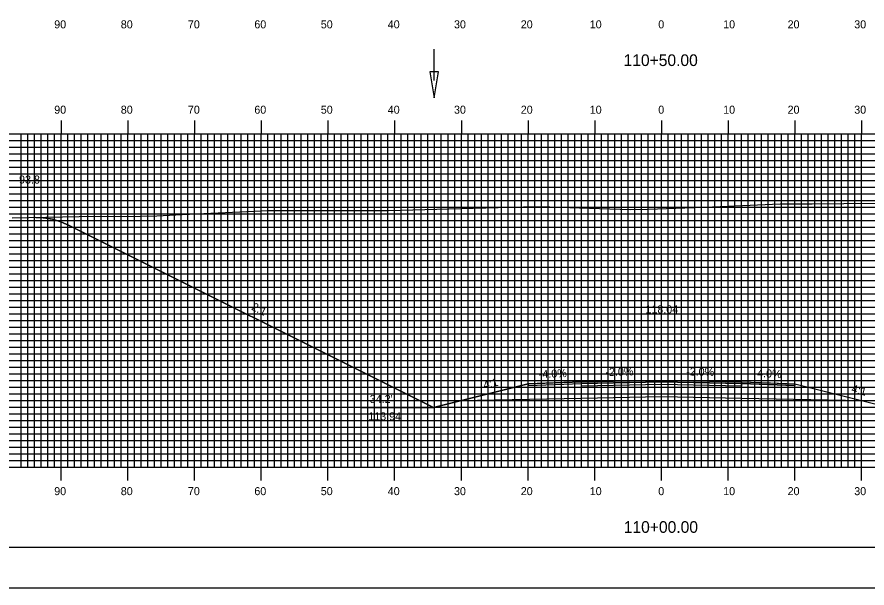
# Model space of a CAD drawing. Extents: x 1769268 to 1769611, y 442591 to 442811.
# Drawn here: x 1769336.9 to 1769464.3, y 442590.5 to 442676.2 of the extents above; entities that cross this region are included whole.
import ezdxf

# ---------------------------------------------------------------- set-up
doc = ezdxf.new("R2010")
doc.units = 0
for name, color, linetype in [('ANNOTATION', 7, 'Continuous'), ('BORDER', 7, 'Continuous'), ('D_Drainage_Ditch_Line', 7, 'Continuous'), ('D_Roadway_Centerline', 7, 'Continuous'), ('D_Roadway_Centerline_Text', 7, 'Continuous'), ('D_Roadway_Edge_Shoulder', 7, 'Continuous'), ('D_Roadway_Edge_TW', 7, 'Continuous'), ('D_Roadway_Pavement', 7, 'Continuous'), ('D_Roadway_SlopeLines', 7, 'Continuous'), ('D_Roadway_SubGrade', 7, 'Continuous'), ('D_Text_Standard', 7, 'Continuous'), ('H_V ANNOTATION', 7, 'Continuous'), ('MAJOR', 7, 'Continuous'), ('MINOR', 7, 'Continuous'), ('PDRAIN', 7, 'Continuous'), ('PLOT BOUNDARY', 7, 'Continuous'), ('S_Roadway_Centerline', 7, 'Continuous')]:
    doc.layers.add(name, color=color, linetype=linetype)

msp = doc.modelspace()

# ---------------------------------------------------------------- linework, layer by layer
at = {"layer": 'BORDER'}
msp.add_lwpolyline([(1769283.9, 442596.67), (1769603.9, 442596.67), (1769603.9, 442806.67), (1769283.9, 442806.67)], close=True, dxfattribs=at)
at = {"layer": 'D_Drainage_Ditch_Line'}
msp.add_line((1769399.44, 442666.66), (1769399.44, 442671.36), dxfattribs=at)
msp.add_lwpolyline([(1769400.1, 442667.97), (1769398.78, 442667.97), (1769399.44, 442664.03)], close=True, dxfattribs=at)
at = {"layer": 'D_Roadway_Centerline'}
msp.add_lwpolyline([(1769339.7, 442646.12), (1769340.82, 442646.07), (1769340.95, 442646.06), (1769341.19, 442646.02), (1769342.2, 442645.84), (1769342.71, 442645.69), (1769343.45, 442645.46), (1769344.7, 442644.92), (1769399.32, 442617.6), (1769399.33, 442617.6), (1769403.33, 442618.6), (1769405.69, 442619.19), (1769413.5, 442621.15), (1769417.29, 442621.3), (1769421.5, 442621.47), (1769433.5, 442621.71), (1769433.5, 442621.71), (1769445.5, 442621.47), (1769449.86, 442621.29), (1769453.5, 442621.15), (1769457.11, 442620.24), (1769463.68, 442618.6), (1769467.68, 442617.6)], dxfattribs=at)
at = {"layer": 'D_Roadway_Edge_Shoulder'}
for points in [[(1769421.5, 442621.47), (1769413.5, 442621.15), (1769413.5, 442620.9), (1769421.5, 442621.22)], [(1769445.5, 442621.47), (1769453.5, 442621.15), (1769453.5, 442620.9), (1769445.5, 442621.22)]]:
    msp.add_lwpolyline(points, close=True, dxfattribs=at)
at = {"layer": 'D_Roadway_Edge_TW'}
msp.add_lwpolyline([(1769421.5, 442621.22), (1769421.5, 442621.47), (1769433.5, 442621.71), (1769445.5, 442621.47), (1769445.5, 442621.22), (1769433.5, 442621.46)], close=True, dxfattribs=at)
at = {"layer": 'D_Roadway_Pavement'}
msp.add_lwpolyline([(1769421.5, 442620.8), (1769421.5, 442621.22), (1769433.5, 442621.46), (1769445.5, 442621.22), (1769445.5, 442620.8), (1769433.5, 442621.04)], close=True, dxfattribs=at)
at = {"layer": 'D_Roadway_SlopeLines'}
for points in [[(1769399.33, 442617.6), (1769344.7, 442644.92), (1769343.45, 442645.46), (1769342.2, 442645.84), (1769340.95, 442646.06), (1769339.7, 442646.12)], [(1769413.5, 442621.15), (1769399.33, 442617.6)], [(1769453.5, 442621.15), (1769467.68, 442617.6)]]:
    msp.add_lwpolyline(points, dxfattribs=at)
at = {"layer": 'D_Roadway_SubGrade'}
msp.add_lwpolyline([(1769421.5, 442618.97), (1769403.33, 442618.6), (1769413.5, 442621.15), (1769413.5, 442620.9), (1769421.5, 442621.22), (1769433.5, 442621.46), (1769445.5, 442621.22), (1769453.5, 442620.9), (1769453.5, 442621.15), (1769463.68, 442618.6), (1769445.5, 442618.97), (1769433.5, 442619.21)], close=True, dxfattribs=at)
at = {"layer": 'MAJOR'}
for p, q in [((1769343.5, 442660.67), (1769343.5, 442658.67)), ((1769353.5, 442660.67), (1769353.5, 442658.67)), ((1769363.5, 442660.67), (1769363.5, 442658.67)), ((1769373.5, 442660.67), (1769373.5, 442658.67)), ((1769383.5, 442660.67), (1769383.5, 442658.67)), ((1769393.5, 442660.67), (1769393.5, 442658.67)), ((1769403.5, 442660.67), (1769403.5, 442658.67)), ((1769413.5, 442660.67), (1769413.5, 442658.67)), ((1769423.5, 442660.67), (1769423.5, 442658.67)), ((1769433.5, 442660.67), (1769433.5, 442658.67)), ((1769443.5, 442660.67), (1769443.5, 442658.67)), ((1769453.5, 442660.67), (1769453.5, 442658.67)), ((1769463.5, 442660.67), (1769463.5, 442658.67)), ((1769293.5, 442658.67), (1769573.5, 442658.67)), ((1769293.5, 442658.67), (1769573.5, 442658.67)), ((1769343.5, 442608.67), (1769343.5, 442658.67)), ((1769353.5, 442608.67), (1769353.5, 442658.67)), ((1769363.5, 442608.67), (1769363.5, 442658.67)), ((1769373.5, 442608.67), (1769373.5, 442658.67)), ((1769383.5, 442608.67), (1769383.5, 442658.67)), ((1769393.5, 442608.67), (1769393.5, 442658.67)), ((1769403.5, 442608.67), (1769403.5, 442658.67)), ((1769413.5, 442608.67), (1769413.5, 442658.67)), ((1769423.5, 442608.67), (1769423.5, 442658.67)), ((1769433.5, 442608.67), (1769433.5, 442658.67)), ((1769443.5, 442608.67), (1769443.5, 442658.67)), ((1769453.5, 442608.67), (1769453.5, 442658.67)), ((1769463.5, 442608.67), (1769463.5, 442658.67)), ((1769293.5, 442653.67), (1769573.5, 442653.67)), ((1769293.5, 442648.67), (1769573.5, 442648.67)), ((1769293.5, 442643.67), (1769573.5, 442643.67)), ((1769293.5, 442638.67), (1769573.5, 442638.67)), ((1769293.5, 442633.67), (1769573.5, 442633.67)), ((1769293.5, 442628.67), (1769573.5, 442628.67)), ((1769293.5, 442623.67), (1769573.5, 442623.67)), ((1769293.5, 442618.67), (1769573.5, 442618.67)), ((1769293.5, 442613.67), (1769573.5, 442613.67)), ((1769293.5, 442608.67), (1769573.5, 442608.67)), ((1769293.5, 442608.67), (1769573.5, 442608.67)), ((1769343.5, 442606.66), (1769343.5, 442608.67)), ((1769353.5, 442606.66), (1769353.5, 442608.67)), ((1769363.5, 442606.66), (1769363.5, 442608.67)), ((1769373.5, 442606.66), (1769373.5, 442608.67)), ((1769383.5, 442606.66), (1769383.5, 442608.67)), ((1769393.5, 442606.66), (1769393.5, 442608.67)), ((1769403.5, 442606.66), (1769403.5, 442608.67)), ((1769413.5, 442606.66), (1769413.5, 442608.67)), ((1769423.5, 442606.66), (1769423.5, 442608.67)), ((1769433.5, 442606.66), (1769433.5, 442608.67)), ((1769443.5, 442606.66), (1769443.5, 442608.67)), ((1769453.5, 442606.66), (1769453.5, 442608.67)), ((1769463.5, 442606.66), (1769463.5, 442608.67))]:
    msp.add_line(p, q, dxfattribs=at)
at = {"layer": 'MINOR'}
for p, q in [((1769337.5, 442608.67), (1769337.5, 442658.67)), ((1769338.5, 442608.67), (1769338.5, 442658.67)), ((1769339.5, 442608.67), (1769339.5, 442658.67)), ((1769340.5, 442608.67), (1769340.5, 442658.67)), ((1769341.5, 442608.67), (1769341.5, 442658.67)), ((1769342.5, 442608.67), (1769342.5, 442658.67)), ((1769344.5, 442608.67), (1769344.5, 442658.67)), ((1769345.5, 442608.67), (1769345.5, 442658.67)), ((1769346.5, 442608.67), (1769346.5, 442658.67)), ((1769347.5, 442608.67), (1769347.5, 442658.67)), ((1769348.5, 442608.67), (1769348.5, 442658.67)), ((1769349.5, 442608.67), (1769349.5, 442658.67)), ((1769350.5, 442608.67), (1769350.5, 442658.67)), ((1769351.5, 442608.67), (1769351.5, 442658.67)), ((1769352.5, 442608.67), (1769352.5, 442658.67)), ((1769354.5, 442608.67), (1769354.5, 442658.67)), ((1769355.5, 442608.67), (1769355.5, 442658.67)), ((1769356.5, 442608.67), (1769356.5, 442658.67)), ((1769357.5, 442608.67), (1769357.5, 442658.67)), ((1769358.5, 442608.67), (1769358.5, 442658.67)), ((1769359.5, 442608.67), (1769359.5, 442658.67)), ((1769360.5, 442608.67), (1769360.5, 442658.67)), ((1769361.5, 442608.67), (1769361.5, 442658.67)), ((1769362.5, 442608.67), (1769362.5, 442658.67)), ((1769364.5, 442608.67), (1769364.5, 442658.67)), ((1769365.5, 442608.67), (1769365.5, 442658.67)), ((1769366.5, 442608.67), (1769366.5, 442658.67)), ((1769367.5, 442608.67), (1769367.5, 442658.67)), ((1769368.5, 442608.67), (1769368.5, 442658.67)), ((1769369.5, 442608.67), (1769369.5, 442658.67)), ((1769370.5, 442608.67), (1769370.5, 442658.67)), ((1769371.5, 442608.67), (1769371.5, 442658.67)), ((1769372.5, 442608.67), (1769372.5, 442658.67)), ((1769374.5, 442608.67), (1769374.5, 442658.67)), ((1769375.5, 442608.67), (1769375.5, 442658.67)), ((1769376.5, 442608.67), (1769376.5, 442658.67)), ((1769377.5, 442608.67), (1769377.5, 442658.67)), ((1769378.5, 442608.67), (1769378.5, 442658.67)), ((1769379.5, 442608.67), (1769379.5, 442658.67)), ((1769380.5, 442608.67), (1769380.5, 442658.67)), ((1769381.5, 442608.67), (1769381.5, 442658.67)), ((1769382.5, 442608.67), (1769382.5, 442658.67)), ((1769384.5, 442608.67), (1769384.5, 442658.67)), ((1769385.5, 442608.67), (1769385.5, 442658.67)), ((1769386.5, 442608.67), (1769386.5, 442658.67)), ((1769387.5, 442608.67), (1769387.5, 442658.67)), ((1769388.5, 442608.67), (1769388.5, 442658.67)), ((1769389.5, 442608.67), (1769389.5, 442658.67)), ((1769390.5, 442608.67), (1769390.5, 442658.67)), ((1769391.5, 442608.67), (1769391.5, 442658.67)), ((1769392.5, 442608.67), (1769392.5, 442658.67)), ((1769394.5, 442608.67), (1769394.5, 442658.67)), ((1769395.5, 442608.67), (1769395.5, 442658.67)), ((1769396.5, 442608.67), (1769396.5, 442658.67)), ((1769397.5, 442608.67), (1769397.5, 442658.67)), ((1769398.5, 442608.67), (1769398.5, 442658.67)), ((1769399.5, 442608.67), (1769399.5, 442658.67)), ((1769400.5, 442608.67), (1769400.5, 442658.67)), ((1769401.5, 442608.67), (1769401.5, 442658.67)), ((1769402.5, 442608.67), (1769402.5, 442658.67)), ((1769404.5, 442608.67), (1769404.5, 442658.67)), ((1769405.5, 442608.67), (1769405.5, 442658.67)), ((1769406.5, 442608.67), (1769406.5, 442658.67)), ((1769407.5, 442608.67), (1769407.5, 442658.67)), ((1769408.5, 442608.67), (1769408.5, 442658.67)), ((1769409.5, 442608.67), (1769409.5, 442658.67)), ((1769410.5, 442608.67), (1769410.5, 442658.67)), ((1769411.5, 442608.67), (1769411.5, 442658.67)), ((1769412.5, 442608.67), (1769412.5, 442658.67)), ((1769414.5, 442608.67), (1769414.5, 442658.67)), ((1769415.5, 442608.67), (1769415.5, 442658.67)), ((1769416.5, 442608.67), (1769416.5, 442658.67)), ((1769417.5, 442608.67), (1769417.5, 442658.67)), ((1769418.5, 442608.67), (1769418.5, 442658.67)), ((1769419.5, 442608.67), (1769419.5, 442658.67)), ((1769420.5, 442608.67), (1769420.5, 442658.67)), ((1769421.5, 442608.67), (1769421.5, 442658.67)), ((1769422.5, 442608.67), (1769422.5, 442658.67)), ((1769424.5, 442608.67), (1769424.5, 442658.67)), ((1769425.5, 442608.67), (1769425.5, 442658.67)), ((1769426.5, 442608.67), (1769426.5, 442658.67)), ((1769427.5, 442608.67), (1769427.5, 442658.67)), ((1769428.5, 442608.67), (1769428.5, 442658.67)), ((1769429.5, 442608.67), (1769429.5, 442658.67)), ((1769430.5, 442608.67), (1769430.5, 442658.67)), ((1769431.5, 442608.67), (1769431.5, 442658.67)), ((1769432.5, 442608.67), (1769432.5, 442658.67)), ((1769434.5, 442608.67), (1769434.5, 442658.67)), ((1769435.5, 442608.67), (1769435.5, 442658.67)), ((1769436.5, 442608.67), (1769436.5, 442658.67)), ((1769437.5, 442608.67), (1769437.5, 442658.67)), ((1769438.5, 442608.67), (1769438.5, 442658.67)), ((1769439.5, 442608.67), (1769439.5, 442658.67)), ((1769440.5, 442608.67), (1769440.5, 442658.67)), ((1769441.5, 442608.67), (1769441.5, 442658.67)), ((1769442.5, 442608.67), (1769442.5, 442658.67)), ((1769444.5, 442608.67), (1769444.5, 442658.67)), ((1769445.5, 442608.67), (1769445.5, 442658.67)), ((1769446.5, 442608.67), (1769446.5, 442658.67)), ((1769447.5, 442608.67), (1769447.5, 442658.67)), ((1769448.5, 442608.67), (1769448.5, 442658.67)), ((1769449.5, 442608.67), (1769449.5, 442658.67)), ((1769450.5, 442608.67), (1769450.5, 442658.67)), ((1769451.5, 442608.67), (1769451.5, 442658.67)), ((1769452.5, 442608.67), (1769452.5, 442658.67)), ((1769454.5, 442608.67), (1769454.5, 442658.67)), ((1769455.5, 442608.67), (1769455.5, 442658.67)), ((1769456.5, 442608.67), (1769456.5, 442658.67)), ((1769457.5, 442608.67), (1769457.5, 442658.67)), ((1769458.5, 442608.67), (1769458.5, 442658.67)), ((1769459.5, 442608.67), (1769459.5, 442658.67)), ((1769460.5, 442608.67), (1769460.5, 442658.67)), ((1769461.5, 442608.67), (1769461.5, 442658.67)), ((1769462.5, 442608.67), (1769462.5, 442658.67)), ((1769293.5, 442657.67), (1769573.5, 442657.67)), ((1769293.5, 442656.67), (1769573.5, 442656.67)), ((1769293.5, 442655.67), (1769573.5, 442655.67)), ((1769293.5, 442654.67), (1769573.5, 442654.67)), ((1769293.5, 442652.67), (1769573.5, 442652.67)), ((1769293.5, 442651.67), (1769573.5, 442651.67)), ((1769293.5, 442650.67), (1769573.5, 442650.67)), ((1769293.5, 442649.67), (1769573.5, 442649.67)), ((1769293.5, 442647.67), (1769573.5, 442647.67)), ((1769293.5, 442646.67), (1769573.5, 442646.67)), ((1769293.5, 442645.67), (1769573.5, 442645.67)), ((1769293.5, 442644.67), (1769573.5, 442644.67)), ((1769293.5, 442642.67), (1769573.5, 442642.67)), ((1769293.5, 442641.67), (1769573.5, 442641.67)), ((1769293.5, 442640.67), (1769573.5, 442640.67)), ((1769293.5, 442639.67), (1769573.5, 442639.67)), ((1769293.5, 442637.67), (1769573.5, 442637.67)), ((1769293.5, 442636.67), (1769573.5, 442636.67)), ((1769293.5, 442635.67), (1769573.5, 442635.67)), ((1769293.5, 442634.67), (1769573.5, 442634.67)), ((1769293.5, 442632.67), (1769573.5, 442632.67)), ((1769293.5, 442631.67), (1769573.5, 442631.67)), ((1769293.5, 442630.67), (1769573.5, 442630.67)), ((1769293.5, 442629.67), (1769573.5, 442629.67)), ((1769293.5, 442627.67), (1769573.5, 442627.67)), ((1769293.5, 442626.67), (1769573.5, 442626.67)), ((1769293.5, 442625.67), (1769573.5, 442625.67)), ((1769293.5, 442624.67), (1769573.5, 442624.67)), ((1769293.5, 442622.67), (1769573.5, 442622.67)), ((1769293.5, 442621.67), (1769573.5, 442621.67)), ((1769293.5, 442620.67), (1769573.5, 442620.67)), ((1769293.5, 442619.67), (1769573.5, 442619.67)), ((1769293.5, 442617.67), (1769573.5, 442617.67)), ((1769293.5, 442616.67), (1769573.5, 442616.67)), ((1769293.5, 442615.67), (1769573.5, 442615.67)), ((1769293.5, 442614.67), (1769573.5, 442614.67)), ((1769293.5, 442612.67), (1769573.5, 442612.67)), ((1769293.5, 442611.67), (1769573.5, 442611.67)), ((1769293.5, 442610.67), (1769573.5, 442610.67)), ((1769293.5, 442609.67), (1769573.5, 442609.67))]:
    msp.add_line(p, q, dxfattribs=at)
at = {"layer": 'PDRAIN'}
msp.add_line((1769388.6, 442617.6), (1769399.33, 442617.6), dxfattribs=at)
at = {"layer": 'PLOT BOUNDARY'}
msp.add_lwpolyline([(1769267.72, 442590.55), (1769607.72, 442590.55), (1769607.72, 442810.55), (1769267.72, 442810.55)], close=True, dxfattribs=at)
at = {"layer": 'S_Roadway_Centerline'}
msp.add_lwpolyline([(1769336.15, 442646.05), (1769346.23, 442646.25), (1769355.41, 442646.33), (1769357.83, 442646.37), (1769361.65, 442646.54), (1769374.58, 442647.14), (1769391.6, 442647.18), (1769392.18, 442647.16), (1769392.57, 442647.17), (1769405.29, 442647.5), (1769412.81, 442647.71), (1769416.75, 442647.7), (1769424.19, 442647.45), (1769428.85, 442647.3), (1769431.51, 442647.34), (1769441.15, 442647.71), (1769451.31, 442648.13), (1769456.07, 442648.17), (1769470.31, 442648.28)], dxfattribs=at)

# ---------------------------------------------------------------- texts
at = {"layer": 'ANNOTATION'}
for s, rotation, p in [('2:1', 333.4347, (1769371.94, 442632.33)), ('-4.0%', 2.2909, (1769415.13, 442622.01)), ('-2.0%', 1.1457, (1769425.11, 442622.34)), ('-2.0%', 358.8542, (1769437.19, 442622.43)), ('-4.0%', 357.7092, (1769447.29, 442622.2)), ('4:1', 14.0377, (1769406.95, 442620.37)), ('4:1', 345.9621, (1769461.9, 442619.91))]:
    msp.add_text(s, height=1.2, rotation=rotation, dxfattribs=at).set_placement(p)
for s, p in [("34.2'", (1769389.77, 442618.29)), ('113.94', (1769389.55, 442615.69))]:
    msp.add_text(s, height=1.2, dxfattribs=at).set_placement(p)
at = {"layer": 'D_Roadway_Centerline'}
for s, p in [('C', (1769433.5, 442621.71)), ('L', (1769433.5, 442621.7))]:
    msp.add_text(s, height=0.0146, dxfattribs=at).set_placement(p)
at = {"layer": 'D_Roadway_Centerline_Text'}
msp.add_text('118.04', height=1.2, dxfattribs=at).set_placement((1769431.1, 442631.74))
at = {"layer": 'D_Text_Standard'}
msp.add_text("93.8'", height=1.2, dxfattribs=at).set_placement((1769337.2, 442651.2))
at = {"layer": 'H_V ANNOTATION'}
for s, height, p in [('90', 1.2, (1769342.47, 442674.47)), ('80', 1.2, (1769352.45, 442674.47)), ('70', 1.2, (1769362.51, 442674.47)), ('60', 1.2, (1769372.47, 442674.47)), ('50', 1.2, (1769382.43, 442674.47)), ('40', 1.2, (1769392.47, 442674.47)), ('30', 1.2, (1769402.4, 442674.47)), ('20', 1.2, (1769412.41, 442674.47)), ('10', 1.2, (1769422.75, 442674.47)), ('0', 1.2, (1769433.02, 442674.47)), ('10', 1.2, (1769442.75, 442674.47)), ('20', 1.2, (1769452.41, 442674.47)), ('30', 1.2, (1769462.4, 442674.47)), ('110+50.00', 1.75, (1769427.82, 442668.82)), ('90', 1.2, (1769342.47, 442661.67)), ('80', 1.2, (1769352.45, 442661.67)), ('70', 1.2, (1769362.51, 442661.67)), ('60', 1.2, (1769372.47, 442661.67)), ('50', 1.2, (1769382.43, 442661.67)), ('40', 1.2, (1769392.47, 442661.67)), ('30', 1.2, (1769402.4, 442661.67)), ('20', 1.2, (1769412.41, 442661.67)), ('10', 1.2, (1769422.75, 442661.67)), ('0', 1.2, (1769433.02, 442661.67)), ('10', 1.2, (1769442.75, 442661.67)), ('20', 1.2, (1769452.41, 442661.67)), ('30', 1.2, (1769462.4, 442661.67)), ('90', 1.2, (1769342.47, 442604.47)), ('80', 1.2, (1769352.45, 442604.47)), ('70', 1.2, (1769362.51, 442604.47)), ('60', 1.2, (1769372.47, 442604.47)), ('50', 1.2, (1769382.43, 442604.47)), ('40', 1.2, (1769392.47, 442604.47)), ('30', 1.2, (1769402.4, 442604.47)), ('20', 1.2, (1769412.41, 442604.47)), ('10', 1.2, (1769422.75, 442604.47)), ('0', 1.2, (1769433.02, 442604.47)), ('10', 1.2, (1769442.75, 442604.47)), ('20', 1.2, (1769452.41, 442604.47)), ('30', 1.2, (1769462.4, 442604.47)), ('110+00.00', 1.75, (1769427.85, 442598.82))]:
    msp.add_text(s, height=height, dxfattribs=at).set_placement(p)

doc.saveas('drawing.dxf')
